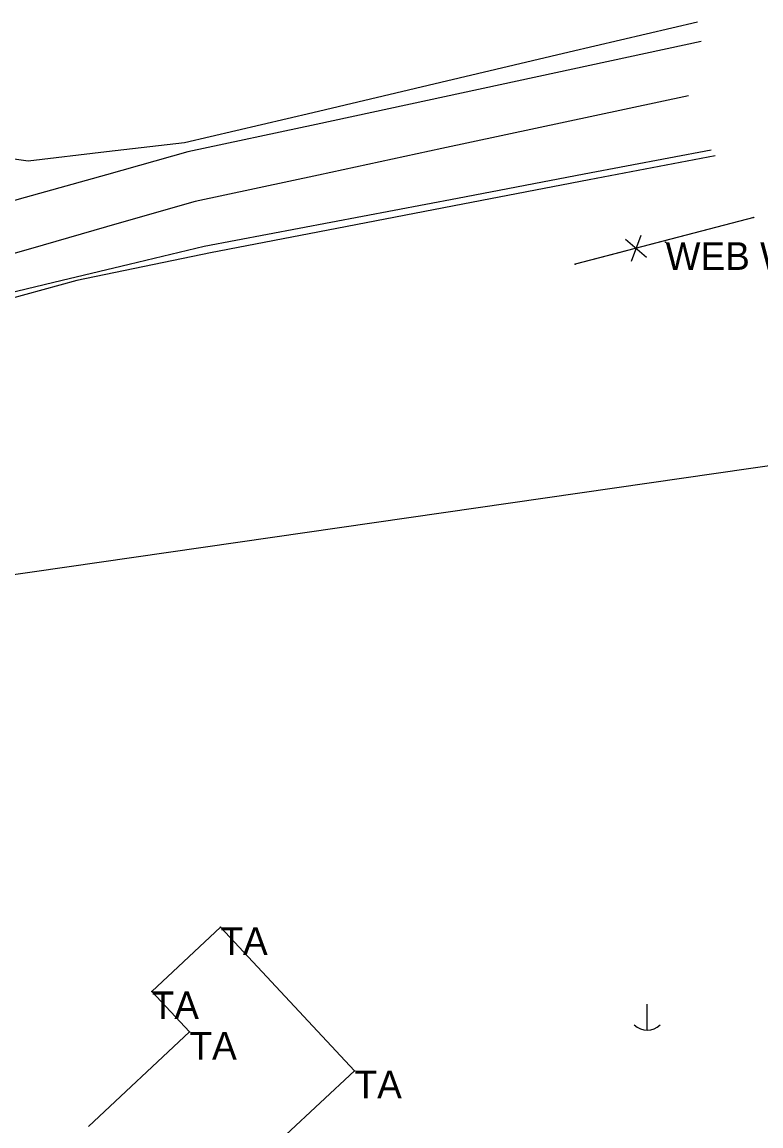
# Model space of a CAD drawing. Extents: x 1660112 to 1662239, y 668919 to 671377.
# Drawn here: x 1661498.3 to 1661631.8, y 670135.7 to 670335.2 of the extents above; entities that cross this region are included whole.
import ezdxf

# ---------------------------------------------------------------- set-up
doc = ezdxf.new("R2010")
doc.units = 0
for name, color, linetype in [('S_BASELINE', 7, 'Continuous'), ('S_BUILDING', 7, 'Continuous'), ('S_BUILDING_ANNOT', 7, 'Continuous'), ('S_FENCE', 7, 'Continuous'), ('S_MSC_PT_SYM', 7, 'Continuous'), ('S_STR_PT_SYM', 7, 'Continuous'), ('S_STREAM', 7, 'Continuous'), ('S_SURVEY_TEXT_ANNOT', 7, 'Continuous'), ('S_UTILITY_POLE', 7, 'Continuous')]:
    doc.layers.add(name, color=color, linetype=linetype)

msp = doc.modelspace()

# ---------------------------------------------------------------- linework, layer by layer
at = {"layer": 'S_BASELINE'}
msp.add_line((1661335.19, 670212.07), (1662115.18, 670324.54), dxfattribs=at)
at = {"layer": 'S_BUILDING'}
for p, q in [((1661521.72, 670159.98), (1661534.14, 670171.59)), ((1661534.14, 670171.59), (1661558.38, 670145.66)), ((1661528.55, 670152.68), (1661521.72, 670159.98)), ((1661510.29, 670135.6), (1661528.55, 670152.68)), ((1661558.38, 670145.66), (1661545.97, 670134.05))]:
    msp.add_line(p, q, dxfattribs=at)
at = {"layer": 'S_FENCE'}
for p, q in [((1661630.51, 670299.86), (1661598.26, 670291.43)), ((1661611.13, 670292.68), (1661607.32, 670295.92)), ((1661611.13, 670292.68), (1661607.32, 670295.92)), ((1661610.1, 670296.64), (1661608.36, 670291.95)), ((1661610.1, 670296.64), (1661608.36, 670291.95))]:
    msp.add_line(p, q, dxfattribs=at)
for points in [[(1661630.51, 670299.86), (1661611.16, 670294.8)], [(1661630.51, 670299.86), (1661611.16, 670294.8)], [(1661607.29, 670293.79), (1661598.26, 670291.43)], [(1661607.29, 670293.79), (1661598.26, 670291.43)]]:
    msp.add_lwpolyline(points, dxfattribs=at)
at = {"layer": 'S_MSC_PT_SYM'}
for points in [[(1661630.51, 670299.86), (1661630.51, 670299.91), (1661630.51, 670299.86), (1661630.46, 670299.86), (1661630.51, 670299.86), (1661630.51, 670299.81), (1661630.51, 670299.86), (1661630.56, 670299.86)], [(1661614.58, 670295.41), (1661614.58, 670295.46), (1661614.58, 670295.41), (1661614.53, 670295.41), (1661614.58, 670295.41), (1661614.58, 670295.36), (1661614.58, 670295.41), (1661614.63, 670295.41)], [(1661598.26, 670291.43), (1661598.26, 670291.48), (1661598.26, 670291.43), (1661598.21, 670291.43), (1661598.26, 670291.43), (1661598.26, 670291.38), (1661598.26, 670291.43), (1661598.31, 670291.43)]]:
    msp.add_lwpolyline(points, dxfattribs=at)
at = {"layer": 'S_STR_PT_SYM'}
for points in [[(1661534.14, 670171.59), (1661534.14, 670171.64), (1661534.14, 670171.59), (1661534.09, 670171.59), (1661534.14, 670171.59), (1661534.14, 670171.54), (1661534.14, 670171.59), (1661534.19, 670171.59)], [(1661521.72, 670159.98), (1661521.72, 670160.03), (1661521.72, 670159.98), (1661521.67, 670159.98), (1661521.72, 670159.98), (1661521.72, 670159.93), (1661521.72, 670159.98), (1661521.77, 670159.98)], [(1661528.55, 670152.68), (1661528.55, 670152.73), (1661528.55, 670152.68), (1661528.5, 670152.68), (1661528.55, 670152.68), (1661528.55, 670152.63), (1661528.55, 670152.68), (1661528.6, 670152.68)], [(1661558.38, 670145.66), (1661558.38, 670145.71), (1661558.38, 670145.66), (1661558.33, 670145.66), (1661558.38, 670145.66), (1661558.38, 670145.61), (1661558.38, 670145.66), (1661558.43, 670145.66)]]:
    msp.add_lwpolyline(points, dxfattribs=at)
at = {"layer": 'S_STREAM'}
for points in [[(1661620.34, 670335.21), (1661597.17, 670329.75), (1661574, 670324.29), (1661550.82, 670318.83), (1661527.65, 670313.37), (1661513.53, 670311.73), (1661499.41, 670310.09), (1661492.64, 670311.04), (1661490.16, 670306.19), (1661483.49, 670303.19), (1661469.16, 670295.94), (1661446.28, 670293.35), (1661423.4, 670290.75), (1661409.17, 670289.53), (1661394.93, 670288.3), (1661370.48, 670288.49), (1661352.9, 670285.18), (1661335.31, 670281.88), (1661320.32, 670280.07), (1661305.33, 670278.26)], [(1661621.04, 670331.68), (1661597.84, 670326.69), (1661574.64, 670321.7), (1661551.44, 670316.71), (1661528.23, 670311.73), (1661513.54, 670307.61), (1661498.85, 670303.49), (1661484.15, 670299.37)], [(1661618.73, 670321.9), (1661596.44, 670317.12), (1661574.16, 670312.34), (1661551.87, 670307.56), (1661529.58, 670302.78), (1661515.84, 670298.83), (1661502.1, 670294.89), (1661488.35, 670290.94)], [(1661622.8, 670312.05), (1661599.9, 670307.69), (1661577, 670303.33), (1661554.1, 670298.98), (1661531.19, 670294.62), (1661517.62, 670291.37), (1661504.05, 670288.12), (1661490.48, 670284.87), (1661476.91, 670281.62), (1661458.63, 670279.27), (1661440.34, 670276.92), (1661422.06, 670274.57), (1661403.77, 670272.22), (1661387.42, 670269.33), (1661371.06, 670266.44), (1661354.71, 670263.56), (1661338.35, 670260.67), (1661316.6, 670255.88), (1661296.46, 670250.86), (1661285.68, 670241.86), (1661274.9, 670232.86), (1661258.9, 670220.78), (1661250.84, 670216.6), (1661237.04, 670210.68)], [(1661623.56, 670311.06), (1661600.76, 670306.67), (1661577.96, 670302.29), (1661555.16, 670297.9), (1661532.36, 670293.52), (1661508.21, 670288.49), (1661492.78, 670284.3), (1661477.36, 670280.12), (1661459.42, 670277.44), (1661441.48, 670274.76), (1661423.55, 670272.09), (1661405.61, 670269.41), (1661388.57, 670266.5), (1661371.54, 670263.59), (1661354.51, 670260.67), (1661337.47, 670257.76), (1661319.37, 670253.79), (1661298.79, 670248.53)]]:
    msp.add_lwpolyline(points, dxfattribs=at)
at = {"layer": 'S_UTILITY_POLE'}
msp.add_line((1661611.21, 670157.7), (1661611.21, 670152.98), dxfattribs=at)
msp.add_arc((1661611.27, 670156.4), 3.41, 226.3972, 313.6028, dxfattribs=at)

# ---------------------------------------------------------------- texts
at = {"layer": 'S_BUILDING_ANNOT'}
for p in [(1661534.14, 670166.59), (1661521.72, 670154.98), (1661528.55, 670147.68), (1661558.38, 670140.66)]:
    msp.add_text('TA', height=5, dxfattribs=at).set_placement(p)
at = {"layer": 'S_SURVEY_TEXT_ANNOT'}
msp.add_text('WEB WIRE MIX POST', height=5, dxfattribs=at).set_placement((1661614.58, 670290.41))

doc.saveas('drawing.dxf')
